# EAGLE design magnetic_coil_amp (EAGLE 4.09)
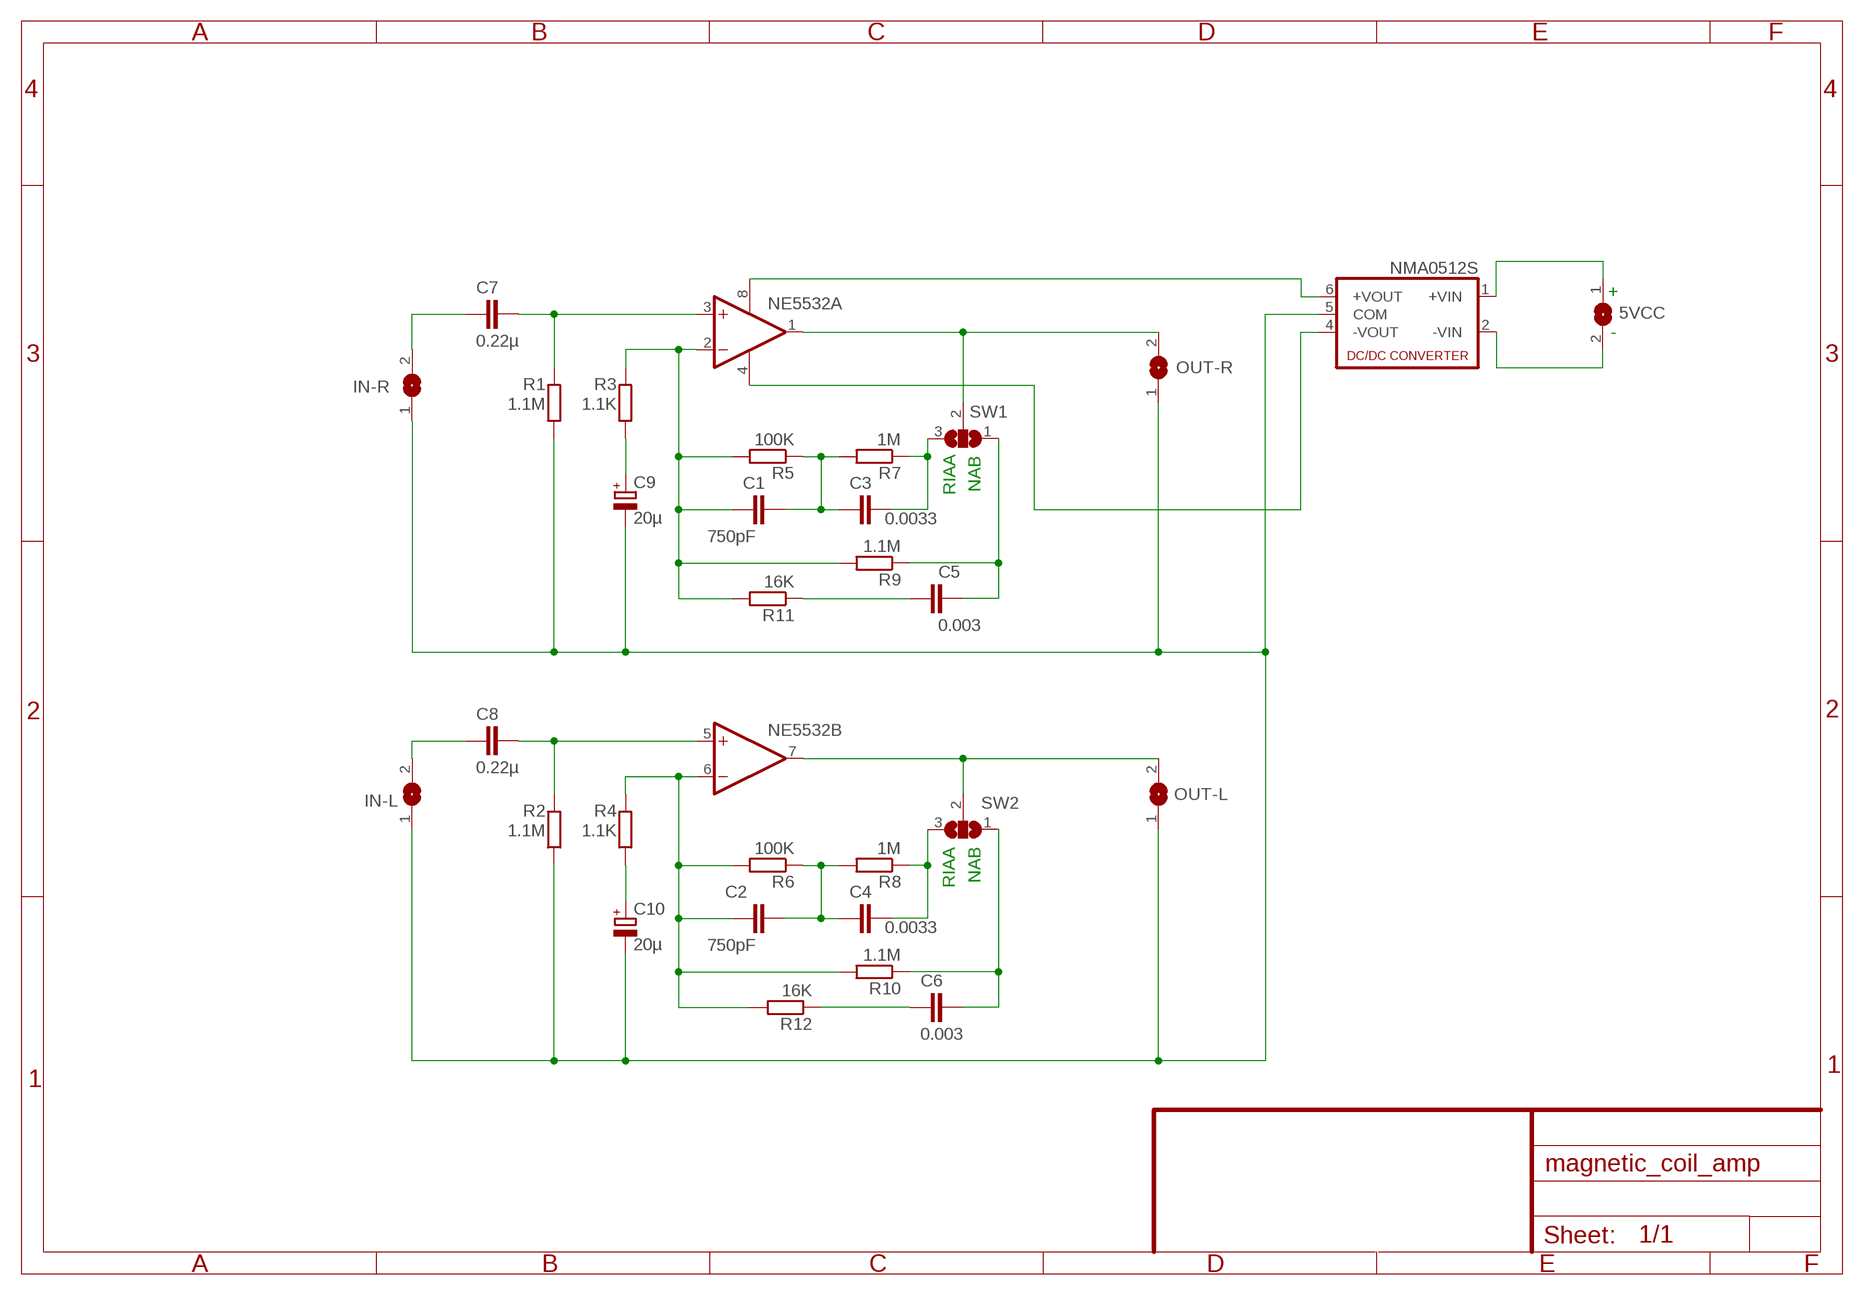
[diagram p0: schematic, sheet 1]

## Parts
5VCC  SJW  [SJW]
C1  750pF  C-EUC1206  [C1206]
C2  750pF  C-EUC1206  [C1206]
C3  0.0033  C-EUC1206  [C1206]
C4  0.0033  C-EUC1206  [C1206]
C5  0.003  C-EUC1206  [C1206]
C6  0.003  C-EUC1206  [C1206]
C7  0.22µ  C-EUC1206  [C1206]
C8  0.22µ  C-EUC1206  [C1206]
C9  20µ  CPOL-EUB45181A  [B45181A]
C10  20µ  CPOL-EUB45181A  [B45181A]
IN-L  SJW  [SJW]
IN-R  SJW  [SJW]
NE5532  NE5532N  [DIL08]
NMA0512S  NMA  [NMA]
OUT-L  SJW  [SJW]
OUT-R  SJW  [SJW]
R1  1.1M  R-EU_M1206  [M1206]
R2  1.1M  R-EU_M1206  [M1206]
R3  1.1K  R-EU_M1206  [M1206]
R4  1.1K  R-EU_M1206  [M1206]
R5  100K  R-EU_M1206  [M1206]
R6  100K  R-EU_M1206  [M1206]
R7  1M  R-EU_M1206  [M1206]
R8  1M  R-EU_M1206  [M1206]
R9  1.1M  R-EU_M1206  [M1206]
R10  1.1M  R-EU_M1206  [M1206]
R11  16K  R-EU_M1206  [M1206]
R12  16K  R-EU_M1206  [M1206]
SW1  SJ2WW  [SJ_2W]
SW2  SJ2WW  [SJ_2W]

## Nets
N$1: C7.2 IN-R.2
N$2: C7.1 NE5532.3(A:+IN) R1.2
N$3: C9.+ R3.1
N$4: C1.2 NE5532.2(A:-IN) R3.2 R5.2 R9.2 R11.2
N$5: NE5532.1(A:OUT) OUT-R.2 SW1.2
N$6: C1.1 C3.2 R5.1 R7.2
N$7: C3.1 R7.1 SW1.3
N$8: C5.2 R11.1
N$9: C5.1 R9.1 SW1.1
N$10: C9.- C10.- IN-L.1 IN-R.1 NMA0512S.5(COM) OUT-L.1 OUT-R.1 R1.1 R2.1
N$11: NE5532.4(P:V-) NMA0512S.4(-VOUT)
N$12: NE5532.8(P:V+) NMA0512S.6(+VOUT)
N$13: 5VCC.1 NMA0512S.1(+VIN)
N$14: 5VCC.2 NMA0512S.2(-VIN)
N$15: C8.2 IN-L.2
N$16: C8.1 NE5532.5(B:+IN) R2.2
N$17: C2.2 NE5532.6(B:-IN) R4.2 R6.2 R10.2 R12.2
N$18: C10.+ R4.1
N$19: C2.1 C4.2 R6.1 R8.2
N$20: NE5532.7(B:OUT) OUT-L.2 SW2.2
N$21: C4.1 R8.1 SW2.3
N$22: C6.1 R10.1 SW2.1
N$23: C6.2 R12.1

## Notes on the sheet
- +
- -
- RIAA | NAB
- RIAA | NAB

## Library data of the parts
5VCC IN-L IN-R OUT-L OUT-R = jumper:SJ: SMD solder JUMPER
C1-C8 = rcl:C-EU: CAPACITOR, European symbol
C9 C10 = rcl:CPOL-EU: POLARIZED CAPACITOR, European symbol
NE5532 = linear:NE5532: AUDIO AMPLIFIER
NMA0512S = dc-dc-converter:NMA: DC-DC CONVERTER
R1-R12 = rcl:R-EU_: RESISTOR, European symbol
SW1 SW2 = jumper:SJ2W: SMD solder JUMPER

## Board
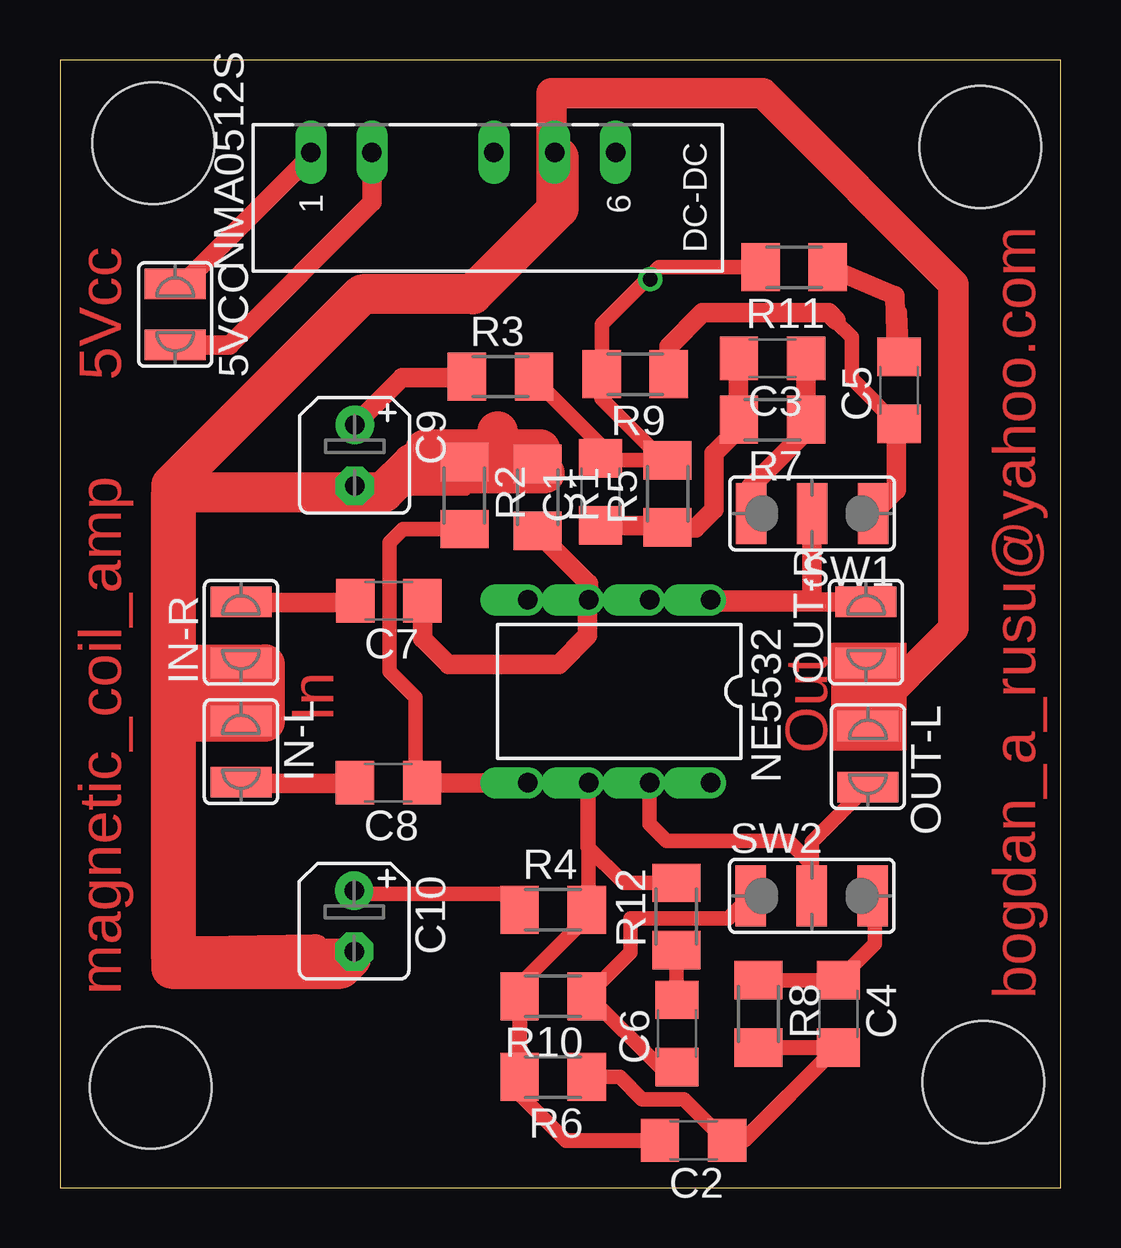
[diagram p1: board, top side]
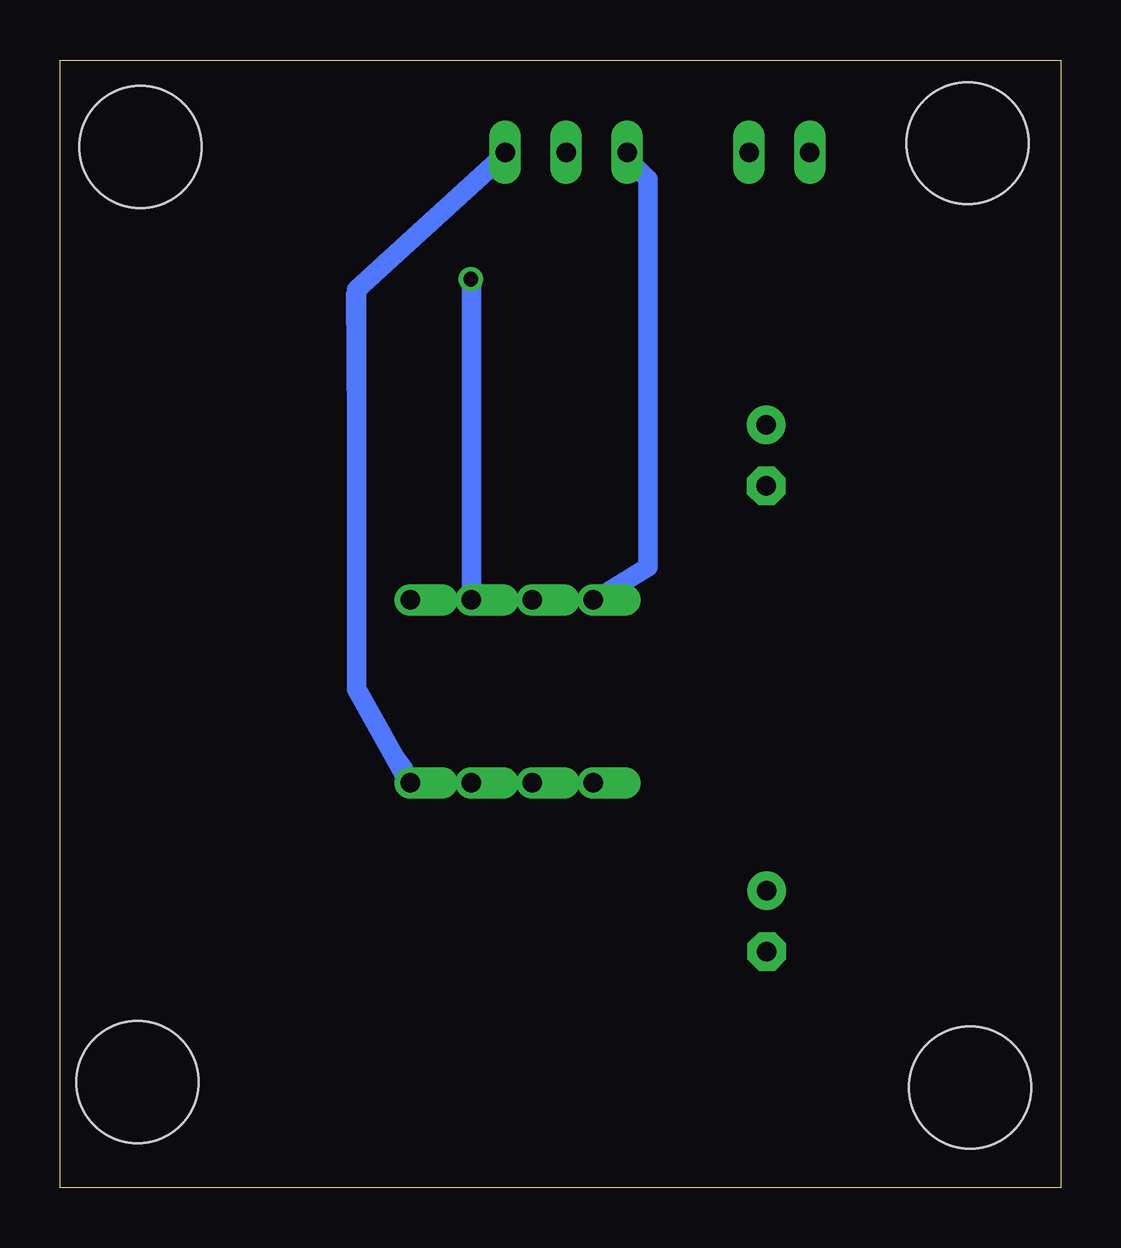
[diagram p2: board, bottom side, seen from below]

Size 41.72 x 47 mm. Coordinates in mm from the lower left corner, seen from the top.
Outline: 0,0 41.72,0 41.72,47 0,47 0,0
Copper layers used: Top, Bottom
Holes 5.08 mm at 3.78,4.17 38.49,4.4 3.89,43.54 38.36,43.38

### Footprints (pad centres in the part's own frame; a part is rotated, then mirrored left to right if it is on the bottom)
SJW = smd 1.27 x 2.54: 1 -1.27,0; 2 1.27,0
C1206 = smd 1.6 x 1.8: 1 -1.4,0; 2 1.4,0
B45181A = drill 0.813 pad 1.6 round: + -1.27,0 | drill 0.813 pad 1.6 octagon: - 1.27,0
DIL08 = drill 0.813 offset: 1 -3.81,-3.81; 2 -1.27,-3.81; 3 1.27,-3.81; 4 3.81,-3.81; 5 3.81,3.81; 6 1.27,3.81; 7 -1.27,3.81; 8 -3.81,3.81
NMA = drill 0.813 long: 1 0,6.35; 2 0,3.81; 4 0,-1.27; 5 0,-3.81; 6 0,-6.35
M1206 = smd 1.6 x 2: 1 -1.4,0; 2 1.4,0
SJ_2W = smd 1.27 x 2.54: 1 -2.54,0; 2 0,0; 3 2.54,0

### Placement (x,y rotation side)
5VCC  4.81,36.39 270 top
C1  22.53,29 90 top
C2  26.41,1.97 180 top
C3  29.7,34.57 180 top
C4  32.45,7.24 270 top
C5  34.98,33.23 90 top
C6  25.72,6.43 90 top
C7  13.71,24.46 180 top
C8  13.69,16.88 180 top
C9  12.28,30.52 270 top
C10  12.26,11.11 270 top
IN-L  7.54,18.17 270 top
IN-R  7.54,23.15 90 top
NE5532  23.31,20.69 180 top
NMA0512S  16.81,43.16 90 top
OUT-L  33.68,17.96 270 top
OUT-R  33.6,23.15 90 top
R1  19.92,28.77 270 top
R2  16.86,28.85 270 top
R3  18.36,33.8 0 top
R4  20.56,11.59 0 top
R5  25.33,28.92 90 top
R6  20.56,4.61 180 top
R7  29.7,32.01 180 top
R8  29.11,7.24 270 top
R9  23.98,33.9 180 top
R10  20.56,7.98 180 top
R11  30.61,38.36 180 top
R12  25.69,11.3 90 top
SW1  31.35,28.1 180 top
SW2  31.34,12.16 0 top

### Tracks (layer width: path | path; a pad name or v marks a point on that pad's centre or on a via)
N$1
  Top 0.813: C7.2 12.3,24.38 7.58,24.38 IN-R.2
N$2
  Top 0.813: C7.1 15.11,22.89 16.19,21.81 20.8,21.81 21.99,23 21.99,24.32 22.04,24.37 NE5532.3 22.04,25.17 19.91,27.3 R1.2
N$3
  Top 0.813: 16.99,33.77 17.03,33.77 | 16.99,33.77 R3.1 | C9.+ 14.26,33.77 16.99,33.77
N$4  (via drill 0.61)
  Top 0.254: v24.6,37.87 24.54,37.93
  Top 0.61: R11.2 24.96,38.36 24.54,37.93 22.59,35.99 22.59,33.95 22.58,33.94 R9.2 22.58,32.89 25.16,30.3 25.18,30.32 R5.2 22.43,30.32 | 22.43,30.32 22.51,30.4 C1.2 22.53,30.96 19.76,33.73 R3.2 | 22.43,30.32 22.41,30.3
  Bottom 0.254: v24.6,37.87 24.6,25.17 NE5532.2
  Bottom 0.813: 24.57,37.78 24.57,24.5
N$5
  Top 0.813: 27.08,24.49 27.08,24.5 | 27.08,24.49 NE5532.1 27.25,24.49 27.26,24.5 31.27,24.5 31.35,24.58 SW1.2 | OUT-R.2 27.16,24.42 27.08,24.49
N$6
  Top 0.813: C1.1 25.15,27.6 25.16,27.61 25.25,27.52 R5.1 25.36,27.49 26.48,27.49 27.26,28.27 27.26,30.6 28.27,31.62 28.27,32.16 | 28.27,32.16 28.27,32.03 R7.2 | C3.2 28.27,34.54 28.27,32.16
N$7
  Top 0.813: SW1.3 28.81,29.22 31.1,31.51 R7.1 31.1,34.36 30.97,34.49 31.05,34.57 C3.1
N$8
  Top 0.813: C5.2 34.9,36.46 34.86,34.85 34.8,37.18 R11.1
N$9
  Top 0.61: 32.34,36.17 32.34,36.11 33,35.45 33,33.71 34.88,31.83 C5.1
  Top 0.813: C5.1 34.94,31.8 34.86,31.8 34.86,29.07 SW1.1 | R9.1 25.38,35.06 26.78,36.46 32.04,36.46 32.34,36.17
N$10
  Top 0.254: 20.79,42.95 NMA0512S.5 | 11.9,28.98 16.98,28.98 16.98,30.25 R2.1 | 19.52,30.25 R1.1 | OUT-R.1 33.49,21.36 33.49,18.82 OUT-L.1 | 5.55,18.82 5.55,20.09 | 5.55,18.82 5.55,9.93 10.63,9.93 11.9,9.93 C10.- | 5.55,20.09 6.82,21.36 IN-R.1 | 5.55,18.82 6.82,18.82 IN-L.1 | 11.9,28.98 5.55,28.98 5.55,20.09 | 11.9,28.98 C9.-
  Top 0.406: 33.49,18.82 33.49,18.71 33.48,18.7 33.48,19.53
  Top 1.27: 10.63,9.93 5.84,9.84 4.94,9.84 4.94,28.39 5.24,29.76 12.84,37.36 17.21,37.36 20.5,40.65 20.5,45.62 29.29,45.62 37.25,37.66 37.25,23.3 33.48,19.53
  Top 1.676: 20.79,42.95 20.79,40.82 17.21,37.24 12.6,37.24 4.64,29.29 4.64,28.99 | 4.64,9.54 4.64,9.12 11.7,9.12 12.12,9.54 4.64,9.54 | 4.64,9.54 4.64,19.41 | 4.64,19.41 4.64,21.81 | 4.64,21.81 4.64,28.99 | 4.64,28.99 13.5,28.99 14.69,30.18 18.22,30.18 | 18.25,31.52 18.22,31.52 18.22,30.18 | 20.02,30.18 18.22,30.18 | 17.09,30.25 16.98,30.25 | 19.52,30.25 17.09,30.25 | 17.09,30.25 17.09,30.3 | 4.64,21.81 8.53,21.81 8.53,19.41 4.64,19.41 | 4.64,19.41 5.54,19.41 5.54,20.61 7.64,20.61 7.64,20.49
N$11
  Bottom 0.254: NE5532.4 17.13,25.83 17.13,42.34 18.25,42.95 NMA0512S.4
N$12
  Bottom 0.254: NE5532.8 27.14,17.55 29.55,20.82 29.67,37.32 NMA0512S.6
N$13
  Top 0.813: NMA0512S.1 10.46,43.09 10.51,43.05 5.12,37.66 5VCC.1
N$14
  Top 0.813: 5VCC.2 7.07,35.12 13.02,41.07 13.02,43.05 13,43.06 NMA0512S.2
N$15
  Top 0.813: C8.2 12.26,16.84 7.6,16.84 IN-L.2
N$16
  Top 0.61: R2.2 14.3,27.45 13.74,26.89 13.74,21.51 14.81,20.43 14.81,17.5 15.41,16.9 19.6,16.9 19.57,16.87 NE5532.5
  Top 0.813: NE5532.5 19.45,16.87 19.42,16.9 19.39,16.87 C8.1
N$17
  Top 0.61: R12.2 23.5,12.7 21.99,14.21 21.99,16.84 22.03,16.87 NE5532.6 22.04,11.62 21.96,11.54 | 21.96,11.54 21.87,11.46 | 21.96,11.54 R4.2 21.96,11.24 19.18,8.47 19.18,7.87 | 19.18,4.76 19.18,3.86 | 19.18,3.86 21.1,1.95 24.98,1.95 C2.2 21.07,1.97 19.18,3.86 | 19.18,7.87 19.16,7.89 R10.2 19.16,4.78 19.18,4.76 | 19.18,4.76 19.18,3.86 | 19.18,4.76 19.18,7.87 | 19.18,4.76 19.16,4.73 R6.2
N$18
  Top 0.61: C10.+ 12.24,12.36 12.24,12.24 18.51,12.24 R4.1
N$19
  Top 0.61: R6.1 23.34,4.61 24.27,3.68 26,3.68 27.8,1.89 28.39,1.89 32.34,5.83 29.35,5.83 29.17,5.65 29.11,5.72 R8.2 32.39,5.84 32.45,5.79 | 32.45,5.79 32.46,5.77 | 32.45,5.79 C4.2 32.41,5.84 28.54,1.97 C2.1
N$20
  Top 0.61: NE5532.7 24.58,15.15 25.28,14.45 30.37,14.45 31.27,13.55 31.27,12.35 31.39,12.24 31.34,12.19 SW2.2 31.34,14.4 33.66,16.72 33.68,16.7 OUT-L.2
N$21
  Top 0.61: C4.1 32.46,8.65 | C4.1 33.96,10.15 33.96,12.23 | R8.1 C4.1 | C4.1 | 33.96,12.23 33.96,12.24 | 33.96,12.23 SW2.3
N$22
  Top 0.61: C6.1 25.01,5.03 22.06,7.98 R10.1 23.79,9.81 23.79,11.22 27.86,11.22 SW2.1
N$23
  Top 0.61: 25.7,9.91 25.7,9.96 | 25.7,9.91 R12.1 | C6.2 25.7,7.84 25.7,9.91
N$24
  Top 1.676: 20.2,29.76 15.23,29.76 | 14.81,29.76 15.23,29.76 | 15.23,29.76 15.23,30.78 20.02,30.78
N$25
  Bottom 0.813: 18.22,43.05 17.21,42.03 17.21,25.88 19.6,24.38
N$26
  Bottom 0.813: 23.19,43.05 29.35,37.42 29.35,20.79 27.08,16.72
(copper drawn outside any net)
  shapes: Top area x1

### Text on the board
Top: 5Vcc | In | Out | magnetic_coil_amp | bogdan_a_rusu@yahoo.com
